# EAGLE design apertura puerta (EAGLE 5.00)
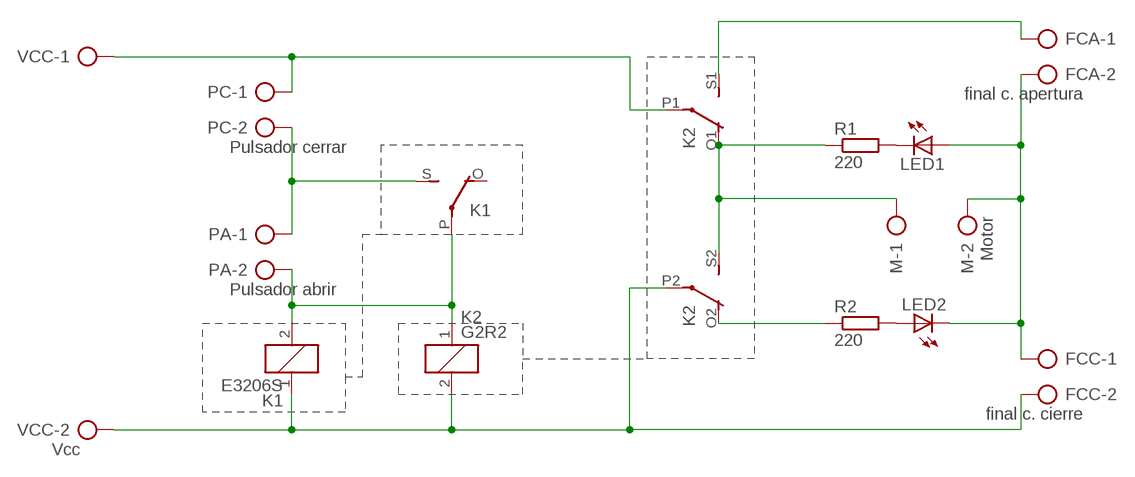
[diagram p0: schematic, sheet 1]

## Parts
FCA  final c. apertura  AK500/2  [AK500/2]
FCC  final c. cierre  AK500/2  [AK500/2]
K1  E3206S  [E3206S]
K2  G2R2  [G2R2]
LED1  LED5MM  [LED5MM]
LED2  LED5MM  [LED5MM]
M  Motor  AK500/2  [AK500/2]
PA  Pulsador abrir  AK500/2  [AK500/2]
PC  Pulsador cerrar  AK500/2  [AK500/2]
R1  220  R-EU_0207/10  [0207/10]
R2  220  R-EU_0207/10  [0207/10]
VCC  Vcc  AK500/2  [AK500/2]

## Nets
N$1: K1.S(2:S) PA.1 PC.2
N$2: K2.P1(2:P) PC.1 VCC.1
N$3: LED1.K(C) R1.2
N$4: K1.2 K1.P(2:P) K2.1 PA.2
N$5: FCC.2 K1.1 K2.2 K2.P2(3:P) VCC.2
N$6: LED2.A R2.2
N$7: FCA.1 K2.S1(2:S)
N$8: FCA.2 FCC.1 LED1.A LED2.K(C) M.2
N$9: K2.O1(2:O) K2.S2(3:S) M.1 R1.1
N$11: K2.O2(3:O) R2.1
Unconnected: K1.O(2:O)

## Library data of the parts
FCA FCC M PA PC VCC = con-ptr500:AK500/2: CONNECTOR
K1 = relay:E3206S: RELAY 1 x switch, Eichhoff/distributor Schukat
K2 = relay:G2R2: RELAY 2 x switch, Omron
LED1 LED2 = led:LED: LED
R1 R2 = rcl:R-EU_: RESISTOR, European symbol

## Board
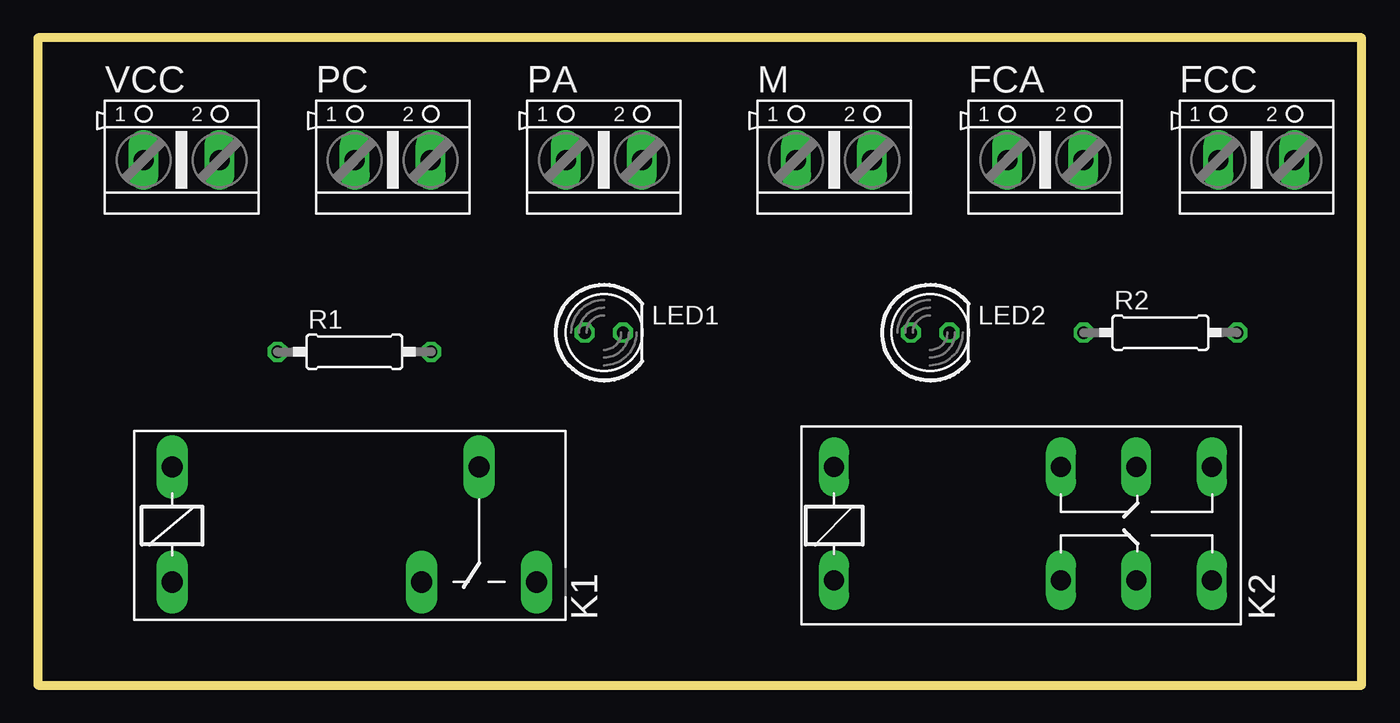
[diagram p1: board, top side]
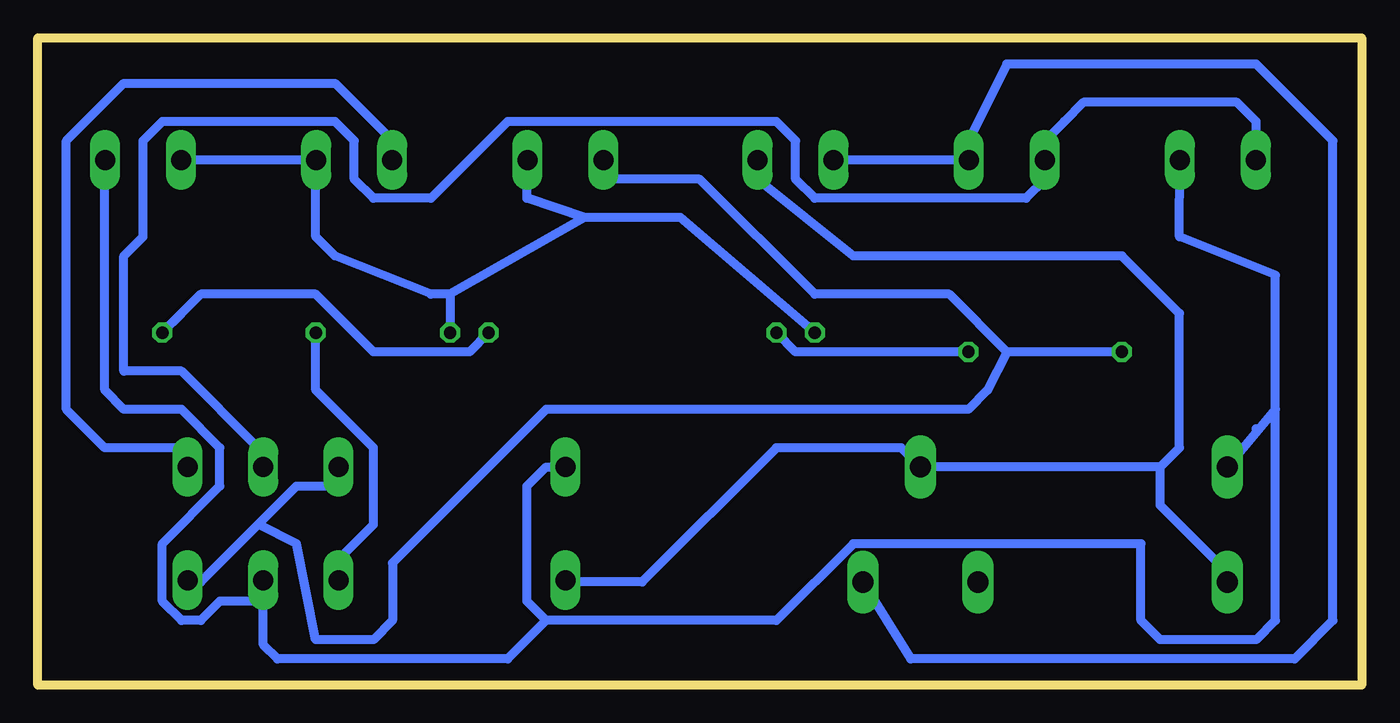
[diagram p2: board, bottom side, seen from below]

Size 87.61 x 42.85 mm. Coordinates in mm from the lower left corner, seen from the top.
Outline: 0,0 87.61,0 87.61,42.85 0,42.85 0,0
Copper layers (1*16): Top 0.035mm / dielectric 1.5mm / Bottom 0.035mm
Design rules "default *": minimum track width 18mil, minimum drill 24mil, track to track 8mil, track to pad 8mil, pad to pad 8mil, via to via 8mil, smd to smd 8mil, copper to edge 40mil, drill to drill 8mil, minimum pad ring 10mil, minimum via ring 8mil, stop-mask expansion 4mil, vias tented up to drill 0mil, thermal gap 10mil

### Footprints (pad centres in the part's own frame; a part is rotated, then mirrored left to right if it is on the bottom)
AK500/2 = drill 1.321 long: 1 -2.515,0; 2 2.515,0
E3206S = drill 1.397 long: 1 -3.175,3.81; 2 -3.175,-3.81; O 13.335,-3.81; P 17.145,3.81; S 20.955,-3.81
G2R2 = drill 1.321 long: 1 -2.54,-3.683; 2 -2.54,3.81; O1 12.471,3.81; O2 12.471,-3.683; P1 17.45,3.81; P2 17.45,-3.683; S1 22.454,3.81; S2 22.454,-3.683
LED5MM = drill 0.813 octagon: A -1.27,0; K 1.27,0
0207/10 = drill 0.813 octagon: 1 -5.08,0; 2 5.08,0

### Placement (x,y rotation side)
FCA  66.67,34.76 0 top
FCC  80.64,34.76 0 top
K1  12.06,10.63 0 top
K2  55.24,10.63 0 top
LED1  37.46,23.33 0 top
LED2  59.05,23.33 0 top
M  52.7,34.76 0 top
PA  37.46,34.76 0 top
PC  23.49,34.76 0 top
R1  20.95,22.06 0 top
R2  74.29,23.33 0 top
VCC  9.52,34.76 0 top

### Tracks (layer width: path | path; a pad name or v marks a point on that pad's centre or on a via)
N$1
  Bottom 0.61: PA.1 PC.2 26.03,36.03 23.49,41.11 6.98,41.11 1.9,36.03 1.9,4.28 4.44,1.74 29.84,1.74 K1.S
N$2
  Bottom 0.61: VCC.1 6.98,36.03 6.98,37.3 8.25,38.57 18.41,38.57 19.68,37.3 20.95,36.03 PC.1 20.95,33.49 22.22,32.22 36.19,32.22 37.46,33.49 37.46,36.03 38.73,37.3 56.51,37.3 61.59,32.22 65.4,32.22 66.67,33.49 66.67,36.03 67.94,37.3 79.37,37.3 80.64,36.03 80.64,29.68 81.91,28.41 81.91,20.79 78.1,20.79 73.02,15.71 K2.P1
N$3
  Bottom 0.61: R1.2 37.46,22.06 LED1.K
N$4
  Bottom 0.61: 13.33,14.44 13.33,11.9 9.52,8.09 K1.2 | PA.2 40,33.49 33.65,28.41 15.87,28.41 12.06,24.6 12.06,15.71 13.33,14.44 | 13.33,14.44 K1.P 30.47,15.71 38.73,15.71 47.62,6.82 52.7,6.82 K2.1
N$5
  Bottom 0.61: 5.71,18.25 5.71,27.14 12.06,29.68 VCC.2 | 6.85,16.88 K1.1 | 5.71,18.25 6.85,16.88 | FCC.2 83.18,33.49 83.18,19.52 81.91,18.25 78.1,18.25 75.56,15.71 75.56,13.17 79.37,9.36 79.37,5.55 78.1,4.28 76.83,4.28 75.56,5.55 73.02,5.55 K2.P2 72.69,2.68 71.75,1.74 56.51,1.74 53.97,4.28 | 53.97,4.28 55.24,5.55 55.24,8.09 55.24,13.17 53.97,14.44 K2.2 | 53.97,4.28 38.73,4.28 33.65,9.36 14.6,9.36 14.6,4.28 13.33,3.01 6.98,3.01 5.71,4.28 5.71,18.25 | 6.85,16.88 6.98,16.98
N$6
  Bottom 0.61: LED2.A 59.05,22.06 65.4,22.06 69.21,25.87 76.83,25.87 R2.2 78.1,24.6
N$7
  Bottom 0.61: K2.S1 78.1,15.71 83.18,15.71 85.72,18.25 85.72,36.03 81.91,39.84 67.94,39.84 64.13,36.03 FCA.1
N$8
  Bottom 0.61: FCC.1 FCA.2 69.21,33.49 69.21,29.68 67.94,28.41 61.59,25.87 60.32,25.87 | LED1.A 45.08,30.95 51.43,30.95 | 51.43,30.95 55.24,32.22 55.24,33.49 M.2 | 51.43,30.95 60.32,25.87 | 60.32,25.87 LED2.K
N$9
  Bottom 0.61: 73.02,10.63 76.83,6.82 K2.S2 | 73.02,10.63 70.48,13.17 67.94,13.17 K2.O1 | R1.1 23.49,22.06 | 23.49,22.06 27.3,25.87 36.19,25.87 43.81,33.49 50.16,33.49 M.1 | 73.02,10.63 70.48,9.36 69.21,3.01 65.4,3.01 64.13,4.28 64.13,8.09 53.97,18.25 51.43,18.25 26.03,18.25 24.76,19.52 23.49,22.06
N$11
  Bottom 0.61: R2.1 69.21,19.52 65.4,15.71 65.4,10.63 67.94,8.09 K2.O2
